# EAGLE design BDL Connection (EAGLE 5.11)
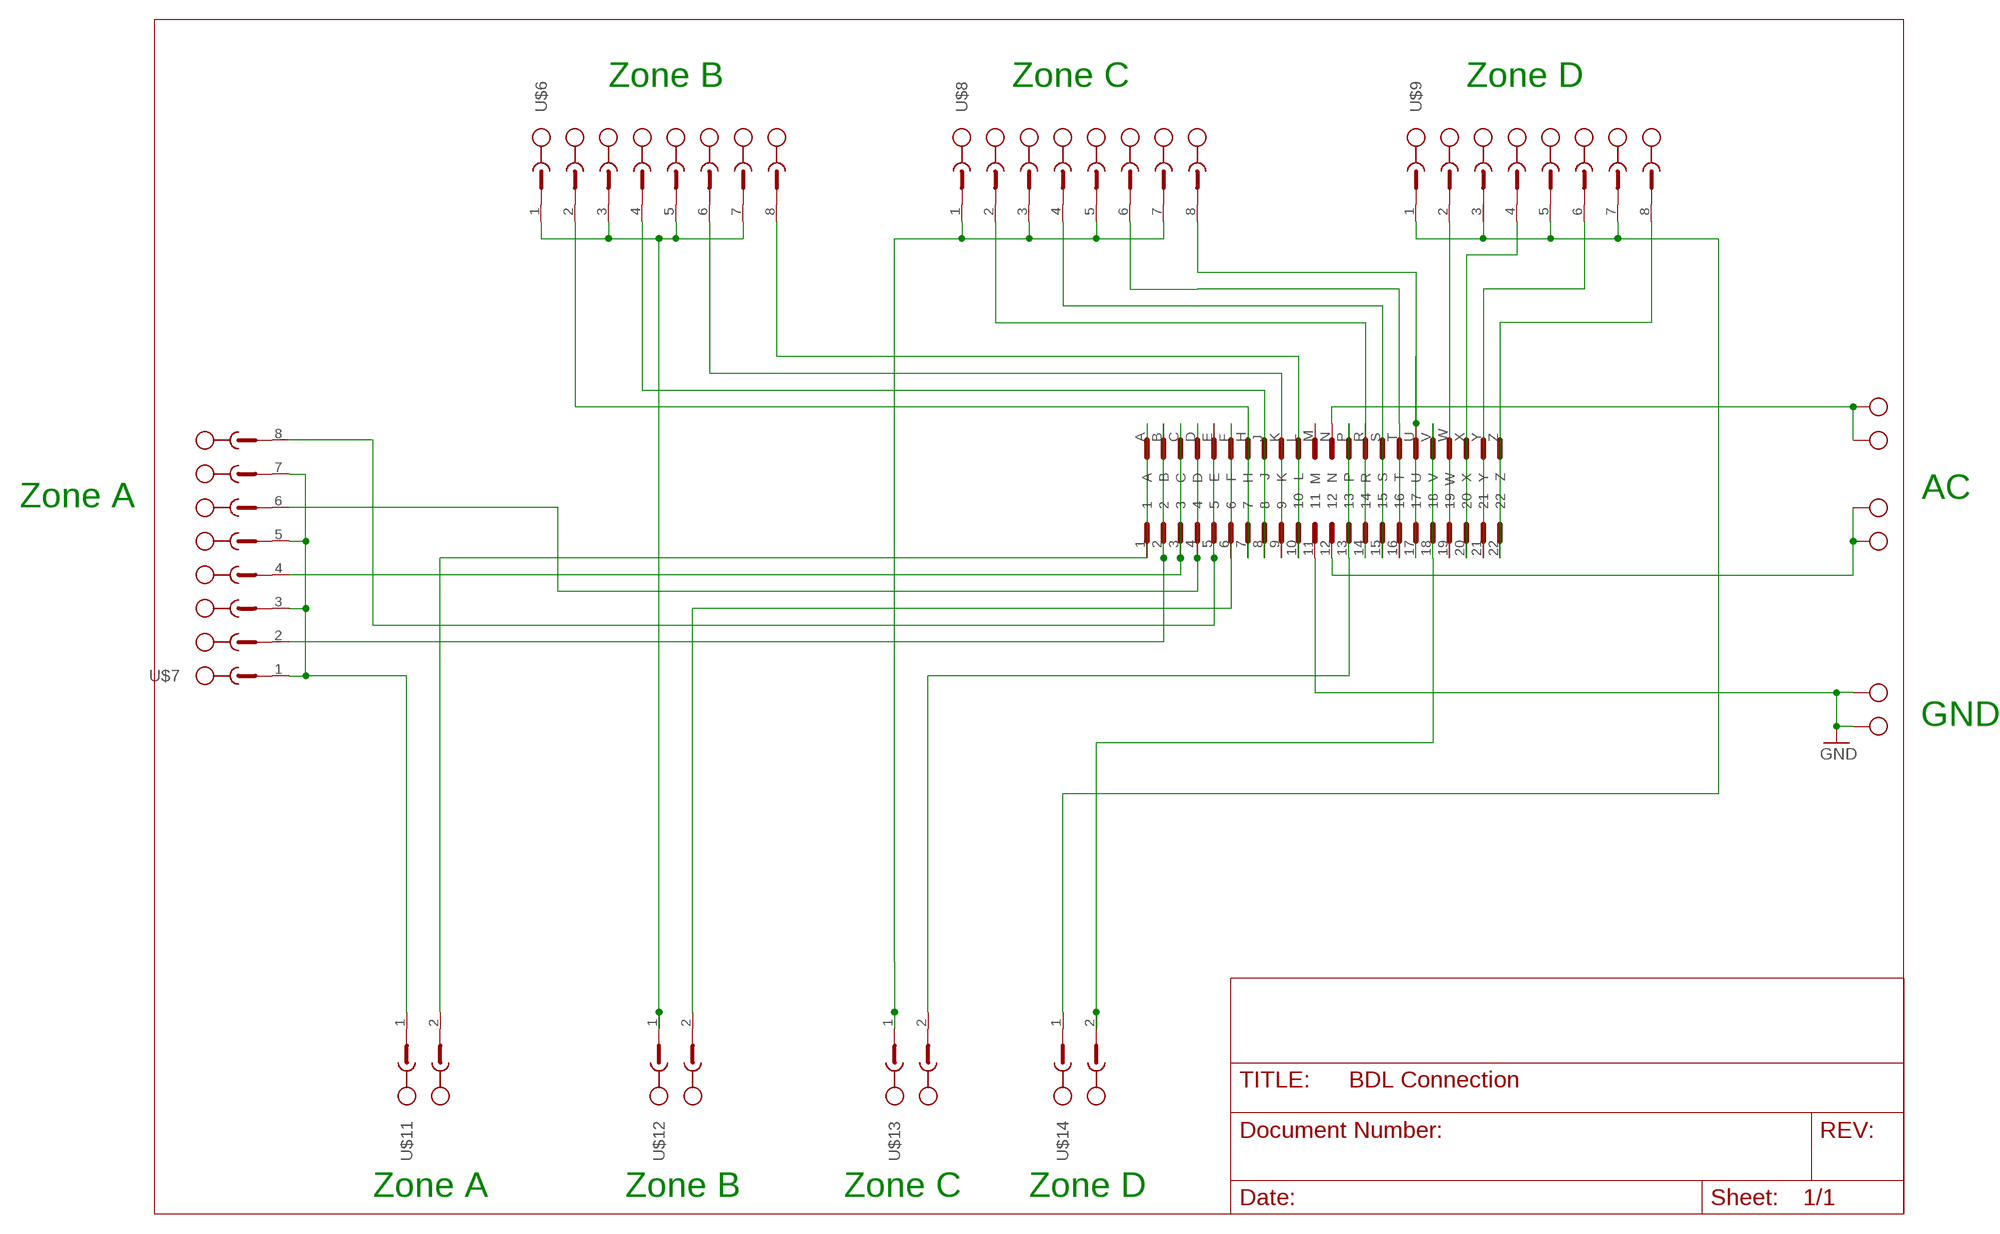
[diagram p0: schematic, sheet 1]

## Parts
U$1  44_PT_EDGE_CON  [44_PT_EDGE_CON]
U$6  PT1_5_8-PVH-50  [PT1_5_8-PVH-50]
U$7  PT1_5_8-PVH-50  [PT1_5_8-PVH-50]
U$8  PT1_5_8-PVH-50  [PT1_5_8-PVH-50]
U$9  PT1_5_8-PVH-50  [PT1_5_8-PVH-50]
U$11  PT1_5_2-PVH-50  [PT1_5_2-PVH-50]
U$12  PT1_5_2-PVH-50  [PT1_5_2-PVH-50]
U$13  PT1_5_2-PVH-50  [PT1_5_2-PVH-50]
U$14  PT1_5_2-PVH-50  [PT1_5_2-PVH-50]
X21  AK300/4  [AK300/4]
X22  AK300/2  [AK300/2]

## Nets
GND: U$1.11 X22.1 X22.2
N$1: U$8.1(SK) U$8.3(SK2) U$8.5(SK4) U$8.7(SK6) U$13.1(SK)
N$2: U$9.1(SK) U$9.5(SK4) U$9.7(SK6) U$14.1(SK)
N$3: U$1.13 U$1.P U$13.2(SK1)
N$4: U$6.1(SK) U$6.3(SK2) U$6.5(SK4) U$6.7(SK6) U$12.1(SK)
N$5: U$1.3 U$1.C U$7.4(SK3)
N$6: U$1.6 U$1.F U$12.2(SK1)
N$8: U$1.2 U$1.B U$7.2(SK1)
N$9: U$1.18 U$1.V U$14.2(SK1)
N$10: U$1.10 U$1.L U$6.8(SK7)
N$11: U$1.4 U$1.D U$7.6(SK5)
N$12: U$7.1(SK) U$7.3(SK2) U$7.5(SK4) U$7.7(SK6) U$11.1(SK)
N$14: U$1.8 U$1.J U$6.4(SK3)
N$15: U$1.9 U$1.K U$6.6(SK5)
N$21: U$1.19 U$1.W U$9.2(SK1)
N$22: U$1.20 U$1.X U$9.4(SK3)
N$23: U$1.21 U$1.Y U$9.6(SK5)
N$24: U$1.14 U$1.R U$8.2(SK1)
N$26: U$1.1 U$1.A U$11.2(SK1)
N$27: U$1.7 U$1.H U$6.2(SK1)
N$28: U$1.22 U$1.Z U$9.8(SK7)
N$29: U$1.16 U$1.T U$8.6(SK5)
N$30: U$1.15 U$1.S U$8.4(SK3)
N$33: U$1.N X21.3 X21.4
N$34: U$1.12 X21.1 X21.2
N$36: U$1.5 U$1.E U$7.8(SK7)
N$40: U$1.17 U$1.U U$8.8(SK7)
Unconnected: U$1.M U$9.3(SK2)

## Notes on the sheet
- Zone B | Zone C | Zone D
- AC
- Zone A
- GND
- Zone A | Zone B | Zone C | Zone D

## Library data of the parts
U$1 = BDL Board:44_PT_EDGE_CON
U$6-U$9 = BDL-Board:PT1_5_8-PVH-50
U$11-U$14 = BDL-Board:PT1_5_2-PVH-50
X21 = con-ptr500:AK300/4: CONNECTOR; OC_FARNELL: unknown; OC_NEWARK: unknown
X22 = con-ptr500:AK300/2: CONNECTOR; OC_FARNELL: unknown; OC_NEWARK: unknown

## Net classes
0 default: width 2.286 mm, drill 0.508 mm, clearance 0.381 mm
1 GND: width 1.27 mm, drill 0.508 mm, clearance 0.381 mm
2 VCC1: width 1.27 mm, drill 0.508 mm, clearance 0.381 mm
3 VCC2: width 1.27 mm, drill 0.508 mm, clearance 0.381 mm

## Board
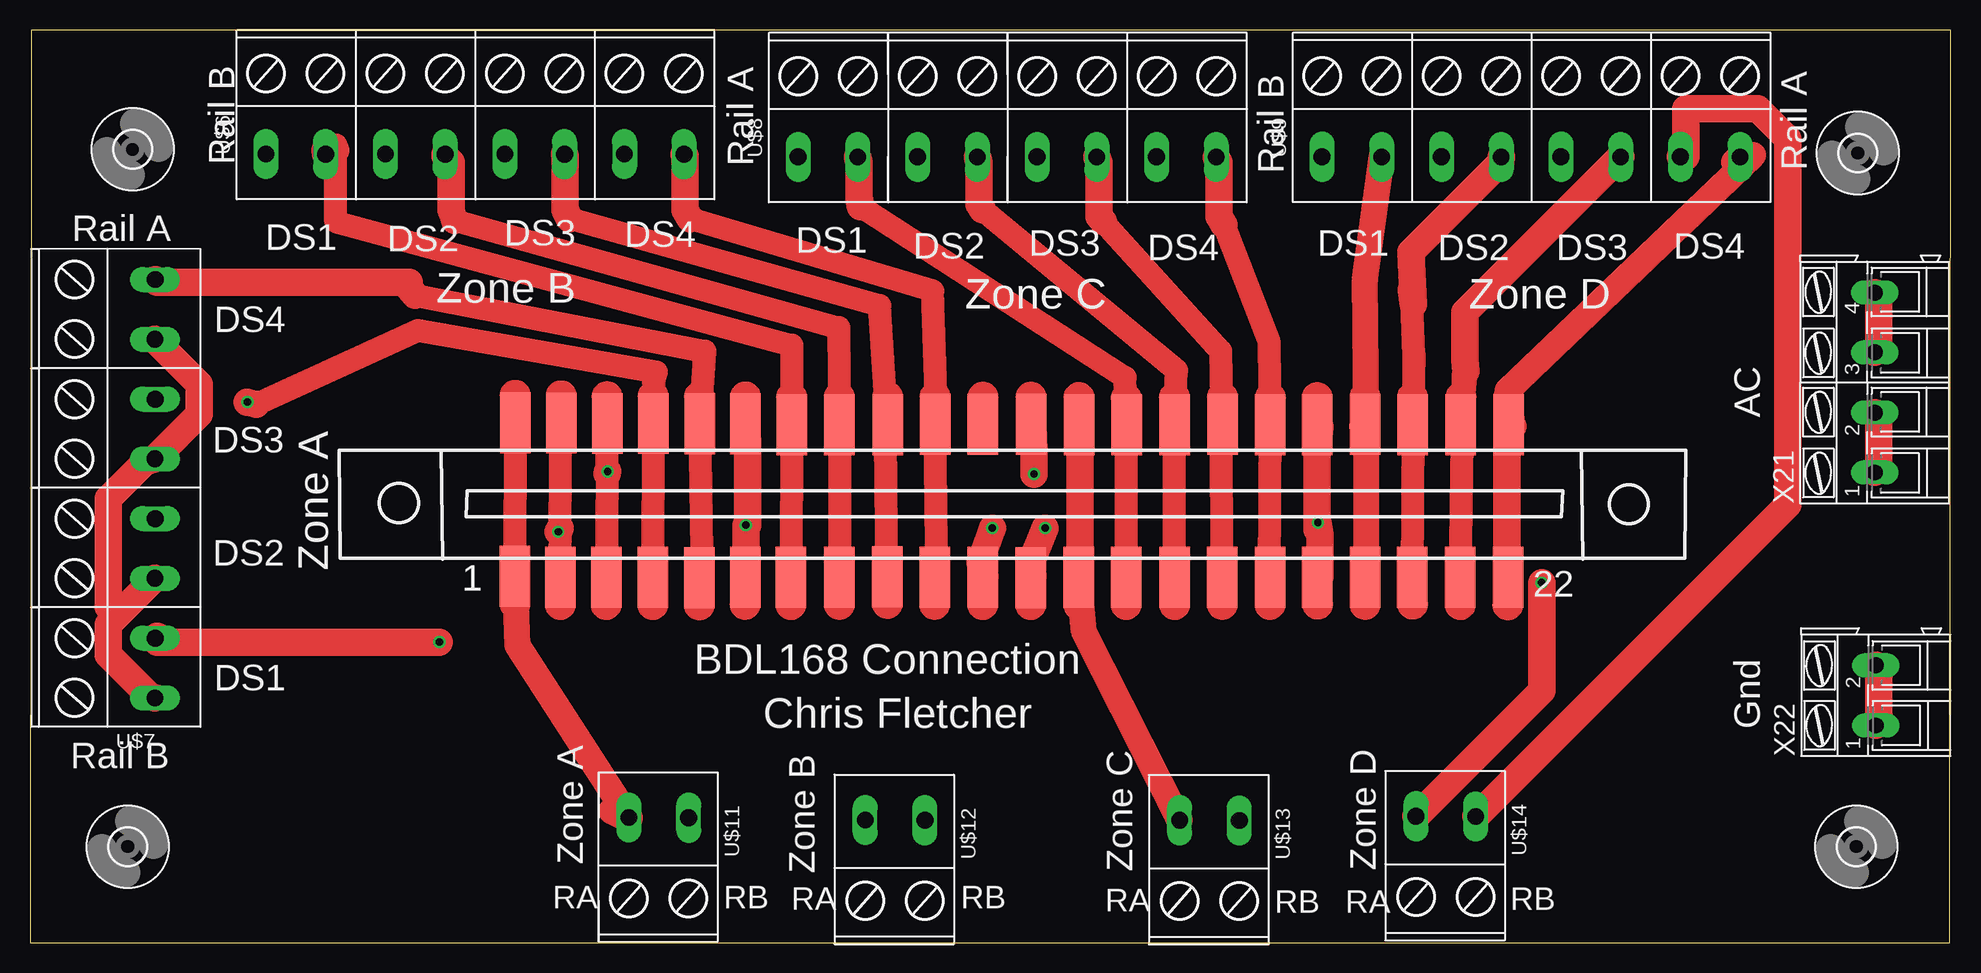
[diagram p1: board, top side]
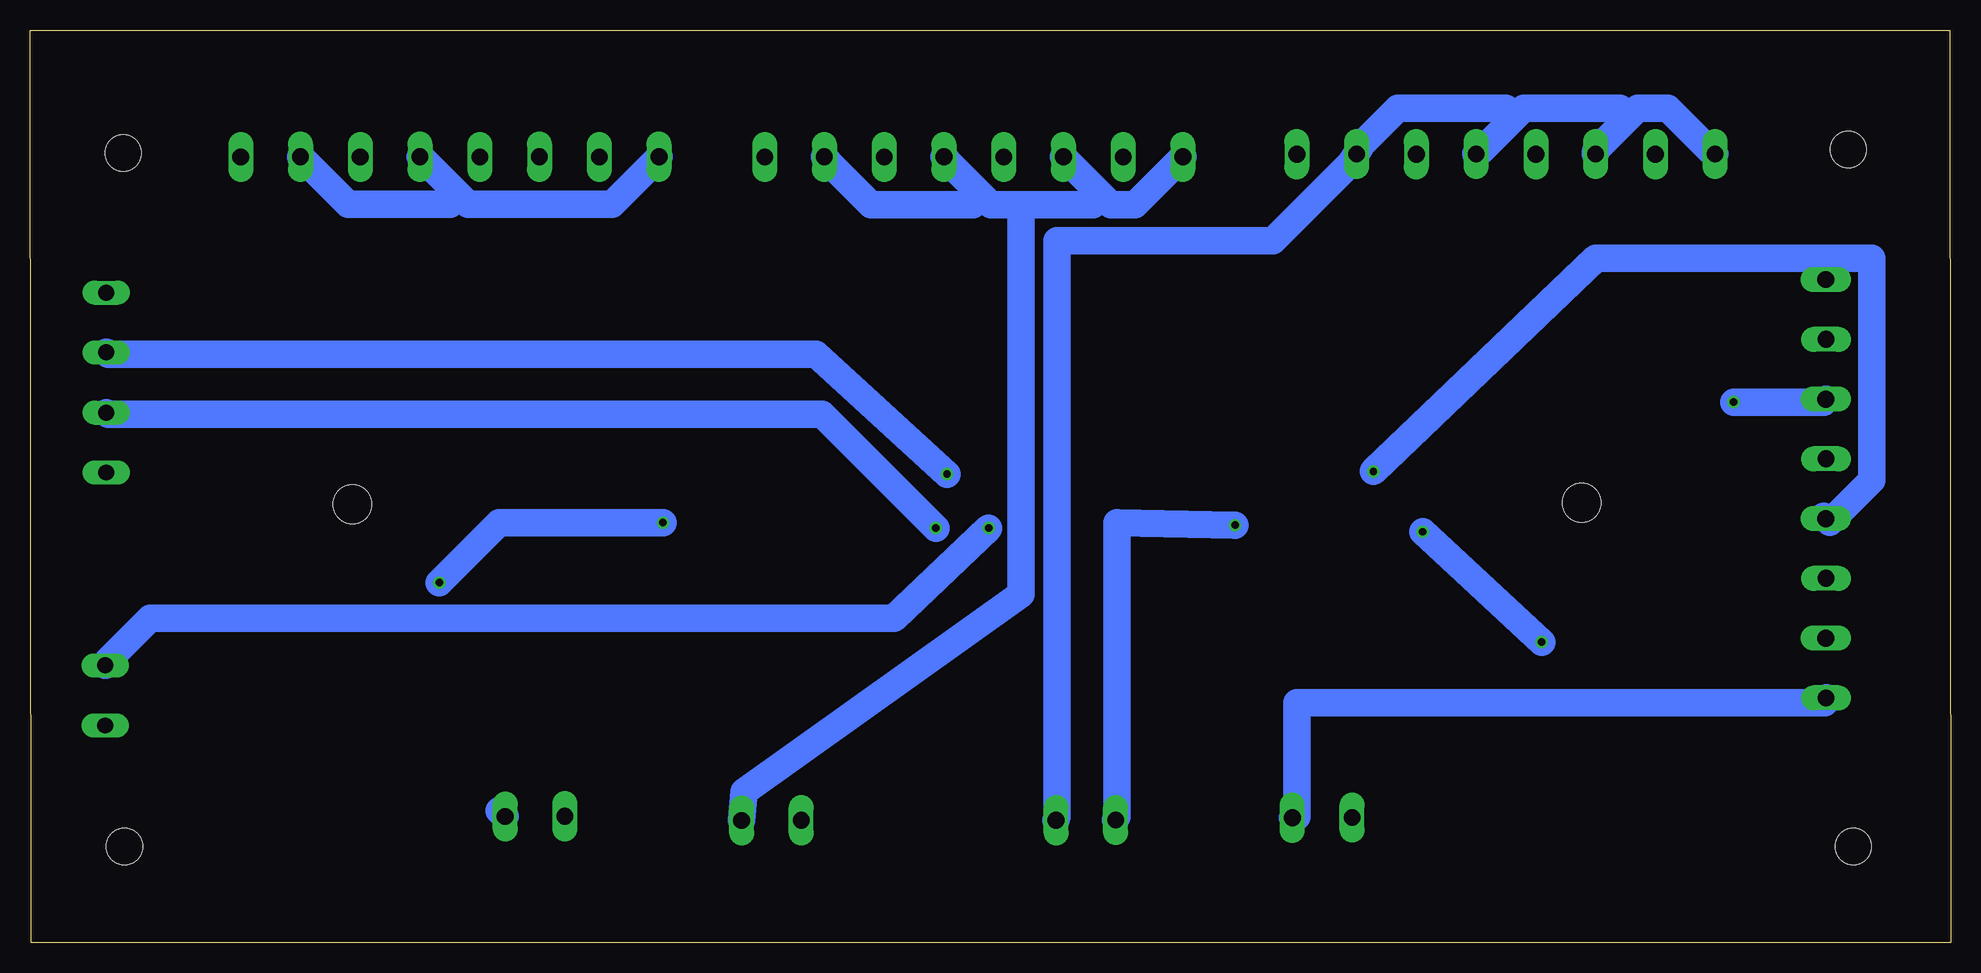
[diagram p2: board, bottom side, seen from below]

Size 160.12 x 76.05 mm. Coordinates in mm from the lower left corner, seen from the top.
Outline: 0,0 160,0 160.12,76.05 0.12,76.05 0,0
Copper layers (1*16): Top 0.035mm / dielectric 1.5mm / Bottom 0.035mm
Design rules "default": minimum track width 10mil, minimum drill 24mil, track to track 8mil, track to pad 8mil, pad to pad 8mil, via to via 8mil, smd to smd 8mil, copper to edge 40mil, drill to drill 8mil, minimum pad ring 10mil, minimum via ring 8mil, stop-mask expansion 4mil, vias tented up to drill 0mil, thermal gap 10mil

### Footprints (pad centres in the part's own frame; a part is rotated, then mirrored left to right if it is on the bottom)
44_PT_EDGE_CON = smd 2.54 x 5.08: 1 41.49,6.01; 2 37.71,6.07; 3 33.87,6.07; 4 30.01,6.07; 5 26.13,6.11; 6 22.29,6.09; 7 18.49,6.09; 8 14.45,6.07; 9 10.47,6.05; 10 6.51,6.07; 11 2.51,6.09; 12 -1.51,6.11; 13 -5.51,6.09; 14 -9.47,6.07; 15 -13.49,6.07; 16 -17.47,6.07; 17 -21.45,6.09; 18 -25.39,6.07; 19 -29.37,6.07; 20 -33.31,6.09; 21 -37.31,6.09; 22 -41.29,6.07; A 41.45,-6.81; B 37.63,-6.77; C 33.79,-6.73; D 29.97,-6.73; E 26.09,-6.71; F 22.27,-6.69; H 18.43,-6.63; J 14.45,-6.63; K 10.43,-6.63; L 6.47,-6.65; M 2.49,-6.67; N -1.53,-6.65; P -5.53,-6.63; R -9.49,-6.61; S -13.49,-6.63; T -17.49,-6.65; U -21.47,-6.61; V -25.39,-6.61; W -29.37,-6.67; X -33.33,-6.61; Y -37.35,-6.63; Z -41.35,-6.63 | hole 3.2: 51.12,-0.12; -51.32,0
3,0 = hole 3: 0,0
PT1_5_8-PVH-50 = drill 1.397 long: 1 22.238,4.96; 2 17.261,4.98; 3 12.277,4.96; 4 7.301,4.98; 5 2.317,4.96; 6 -2.659,4.98; 7 -7.643,4.96; 8 -12.619,4.98
PT1_5_2-PVH-50 = drill 1.397 long: 1 1.917,2.42; 2 -3.059,2.44
AK300/4 = drill 1.321 long: 1 -7.493,0; 2 -2.515,0; 3 2.515,0; 4 7.493,0
AK300/2 = drill 1.321 long: 1 -2.515,0; 2 2.489,0

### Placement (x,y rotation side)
U$1  81.91,36.53 180 top
U$2  [3,0]  8.55,66.1 0 top
U$3  [3,0]  152.36,65.8 0 top
U$4  [3,0]  8.14,8 0 top
U$5  [3,0]  152.24,8 0 top
U$6  41.9,70.68 180 top
U$7  5.45,42.63 270 top
U$8  86.26,70.44 180 top
U$9  129.93,70.45 180 top
U$11  52.98,7.98 0 top
U$12  72.68,7.78 0 top
U$13  98.89,7.76 0 top
U$14  118.59,8.09 0 top
X21  153.77,46.67 90 top
X22  153.85,20.61 90 top

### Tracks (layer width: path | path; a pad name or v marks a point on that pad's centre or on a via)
GND  (via drill 0.61)
  Top 2.286: X22.1 154.12,18.55 154.12,23.05 X22.2 | v80.21,34.55 79.18,31.65 79.62,30.55 U$1.11
  Bottom 2.286: v80.21,34.55 88.12,27.05 150.12,27.05 153.62,23.55 X22.2
N$1
  Bottom 2.286: 70.75,62.25 73.5,65 U$8.3 | 70.75,62.25 70,61.5 68,61.5 64.5,65 U$8.1 | 80.75,62.25 80,61.5 77.5,61.5 | 80.75,62.25 83.5,65 U$8.5 | 77.5,61.5 71.5,61.5 70.75,62.25 | U$8.7 93.5,65 90,61.5 81.5,61.5 80.75,62.25 | U$13.1 100.61,12.57 77.5,29.05 77.5,61.5
N$2
  Top 2.286: U$14.1 121,11 146.5,36.5 146.5,67 144,69.5 138,69.5 138,65.5 U$9.7
  Bottom 2.286: 124.37,62.3 127.12,65.05 U$9.5 | 124.37,62.3 123.62,61.55 111.62,61.55 108.12,65.05 U$9.1 | U$9.7 137.12,65.05 133.62,61.55 125.12,61.55 124.37,62.3 | U$14.1 121,11
N$3
  Top 2.184: U$1.13 87.87,25.9 U$13.2
  Top 2.286: U$1.13 87.5,30.5 87.5,43 U$1.P
N$4
  Bottom 2.286: 26.87,68.8 29.62,66.05 U$6.3 | 26.87,68.8 26.12,69.55 23.62,69.55 20.12,66.05 U$6.1 | 36.37,68.8 35.62,69.55 27.62,69.55 26.87,68.8 | 36.37,68.8 39.12,66.05 U$6.5 | 36.37,68.8 37.12,69.55 46.12,69.55 49.12,66.55 U$6.7 50,65 56.5,58.5 74.5,58.5 74.5,10.5 U$12.1
N$5  (via drill 0.61)
  Top 1.93: U$1.3 48.09,39.05 U$1.C
  Top 2.286: v48.14,39.26 48.09,39.05
  Bottom 2.286: v48.14,39.26 29.62,57.05 6.62,57.05 6.62,38.55 10.12,35.05 10.62,35.55 U$7.4
N$6  (via drill 0.61)
  Top 2.286: U$1.6 59.69,30.3 59.69,34.3 v59.67,34.79 59.8,34.76 59.8,41.76 U$1.F
  Bottom 2.286: v59.67,34.79 69.5,35 69.5,10.5 U$12.2
N$8  (via drill 0.61)
  Top 1.93: U$1.B 44.17,34.54 44.11,29.54 U$1.2
  Top 2.286: v34.12,25.05 10.62,25.05 10.62,25.55 U$7.2 | v44.03,34.24 44.17,34.54
  Bottom 2.286: v34.12,25.05 v44.03,34.24
N$9  (via drill 0.61)
  Top 2.286: v126,30 126,21 116,11 U$14.2 | U$1.18 107.5,30.5 107.5,34 v107.36,35 107.28,34.46 107.28,40.96 107.5,43 U$1.V
  Bottom 2.286: v126,30 121,35 v107.36,35
N$10
  Top 1.93: U$1.10 75.61,29.66 U$1.L 75.61,43.28 75.24,54.32 55.02,60.33
  Top 2.286: U$6.8 54.62,65.55 54.62,61.05 55.02,60.33
N$11  (via drill 0.61)
  Top 1.93: U$1.4 U$1.D 51.96,43.28 51.96,46.71 52.2,47.57 32.35,51.01 18.87,44.87
  Top 2.286: v18.12,45.05 18.87,44.87
  Bottom 2.286: v18.12,45.05 10.62,45.05 U$7.6
N$12
  Top 2.286: U$7.7 10.62,50.05 14.12,46.55 14.12,44.05 10.62,40.55 U$7.5 9.5,40 6.5,37 6.5,28 7.25,27.25 | 7.25,27.25 10,30 U$7.3 | 7.25,27.25 6.5,26.5 6.5,24 10,20.5 U$7.1
  Bottom 2.286: U$11.1 54.5,10.5 54.5,20 10.5,20 U$7.1
N$14
  Top 1.93: U$1.8 U$1.J 67.4,51.25 35.41,60.21
  Top 2.286: U$6.4 34.62,65.55 35.12,65.05 35.12,61.05 35.41,60.21
N$15
  Top 1.93: U$1.K 71.32,43.03 71.44,43.4 | 71.44,43.4 71.32,42.79 71.32,42.05 U$1.9 | 71.44,43.4 70.83,53.09 44.97,60.34
  Top 2.286: U$6.6 44.62,65.55 44.62,61.05 44.97,60.34
N$21
  Top 2.184: U$1.19 111.4,30.46 111.4,43.05 111.4,43.77 111.28,55.24 U$9.2
  Top 2.286: U$1.W 111.12,43.05 111.4,43.05
N$22
  Top 1.93: U$1.20 115.36,48.97 | 115.36,48.97 115.15,54.42 | 115.36,48.97 U$1.X
  Top 2.286: U$9.4 122.62,65.05 115.12,57.55 115.33,53.19 115.15,54.42
N$23
  Top 1.93: U$1.21 119.49,47.45 119.7,47.6 U$1.Y
  Top 2.286: U$9.6 132.12,65.05 119.62,52.55 119.62,48.55 119.7,47.6
N$24
  Top 1.93: U$1.14 U$1.R 91.29,47.08 69.23,61.31
  Top 2.286: U$8.2 69.12,65.05 69.12,62.05 69.23,61.31
N$26
  Top 1.93: U$1.1 U$1.A
  Top 2.184: U$1.1 40.64,24.8 U$11.2
  Top 2.286: U$11.2 49.5,10.5 48.5,11
N$27
  Top 1.93: U$1.7 U$1.H 63.48,49.78 25.49,60.08 25.49,66.05 25.49,66.46
  Top 2.286: U$6.2 24.62,66.05 25.49,66.05
N$28
  Top 2.184: 123.62,43.05 123.16,45.99 143.64,65.63 U$9.8
  Top 2.286: U$9.8 142.12,65.05 | 123.62,43.05 U$1.Z 123.12,42.05 123.12,30.55 U$1.22
N$29
  Top 1.93: U$1.16 99.26,43.77 99.38,43.89 U$1.T 99.26,49.29 89.46,60.08
  Top 2.286: U$8.6 89.12,65.05 89.12,60.55 89.46,60.08
N$30
  Top 1.93: U$1.15 U$1.S 95.58,47.69 79.4,61.06
  Top 2.286: U$8.4 79.12,65.05 79.12,61.55 79.4,61.06
N$33  (via drill 0.61)
  Top 2.286: X21.3 154.12,49.55 154.12,54.05 X21.4 | v83.69,39.05 83.69,41.01 83.62,43.05 U$1.N
  Bottom 2.286: v83.69,39.05 94.62,49.05 153.62,49.05 X21.3
N$34  (via drill 0.61)
  Top 2.286: X21.1 154.12,39.55 154.12,44.05 X21.2 | v84.62,34.55 83.48,31.75 83.62,30.55 U$1.12
  Bottom 2.286: v84.62,34.55 94.12,44.05 153.62,44.05 X21.2
N$36
  Top 1.93: U$1.5 56,29.9 U$1.E 56.24,49.28 32.1,53.95
  Top 2.286: U$7.8 10.62,55.05 31.62,55.05 31.62,54.55 32.1,53.95
N$40
  Top 1.93: U$1.17 103.3,30.64 U$1.U 103.3,50.02 99.5,59.84
  Top 2.286: U$8.8 99.12,65.05 99.12,60.55 99.5,59.84

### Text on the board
tPlace: Rail B | Rail A | Rail B | Rail A | Rail A | DS1 | DS2 | DS3 | DS4 | DS1 | DS2 | DS3 | DS4 | DS1 | DS2 | DS3 | DS4 | Zone B | Zone C | Zone D | DS4 | DS3 | DS2 | Zone A | 1 | 22 | BDL168 Connection | DS1 | Chris Fletcher | Gnd AC | Rail B | Zone A | Zone B | Zone C | Zone D | RA | RB | RA | RB | RA | RB | RB | RA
